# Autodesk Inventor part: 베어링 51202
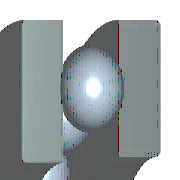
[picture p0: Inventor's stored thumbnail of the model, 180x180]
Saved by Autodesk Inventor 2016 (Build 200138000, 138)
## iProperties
Created: 2012-02
Part Number: 베어링 51202
Material: 강철, 연강
Description: 롤링 베어링 - 플랫 뒷면이 있는 스러스트 볼 베어링
Document SubType Name: Modeling
Standard: KS B 2022
Designer: mduedu
Standards Organization: KS
Language: ko-KR
Size Designation: 51202 - 15 x 32 x 12
Categories: <MemberInstance><Categories><Category DisplayName="샤프트 부품" InternalName="7f7aeb1f-a693-4053-b835-cee3144e0d98" Mnemonic="SHFT"><Category DisplayName="베어링" Inter
Density: 1 g/cm^3
Appearance: 진녹색
IsCustomPart: 1
Author: mduedu
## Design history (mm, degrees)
sketch "스케치1" dims "d3" = 5.28 (= 0.44 x KB)
  geometry: L1 (6, 9.61)-(6, 14.89); L2 (8.64, 12.25)-(3.36, 12.25); L3 (3.6, 16)-(0, 16); L4 (3.6, 7.5)-(0, 7.5); L5 (8.4, 13.35)-(8.4, 16); L6 (8.4, 16)-(12, 16); L7 (12, 16)-(12, 8.5); L8 (12, 8.5)-(8.4, 8.5); L9 (8.4, 8.5)-(8.4, 11.15); L10 (3.6, 16)-(3.6, 13.35); L11 (3.6, 11.15)-(3.6, 7.5); L12 (-1.8, 0)-(10.8, 0) reference; L13 (0, -0.022)-(0, 5.522) reference; 1 further point
  constraints: 22 end point, 5 perpendicular, 2 equal length, 2 midpoint, 2 parallel, 2 point on line, 1 collinear, 10 other
  dimensions: "d8" = 4.8 diameter of L11 L1 (= 0.4 x KB); "d11" = 15 diameter of L4 L12 (= WD); "d12" = 17 diameter of L8 L12 (= KAD1); "d13" = 32 diameter of L3 L12 (= KID1); "d14" = 32 diameter of L6 L12 (= BD); "d15" = 24.5 diameter of point (6, 12.25) L12 (= 0.5 x KID1 + 0.5 x KAD1); "d16" = 6 distance from line of point (6, 12.25) L13 (= 0.5 x KB); "d18" = 12 distance between parallel lines of L7 L13 (= KB)
revolve "본체" stored, may be unused: angle "d9" = 90 deg
revolve "볼" stored, may be unused: angle "d10" = 90 deg
pattern_circular "IDS_ARRAYBALL[SIMPL:T]" dims angle "d2" = 360 deg
body "Solid1"
fillet "모깎기1" dims "d4" = 0.6 (= KRS)
fillet "모깎기2" dims "d5" = 0.6 (= KRS)
other parameters: "WD" = 15 [user parameter; used in 2 equation terms], "KAD1" = 17 [user parameter; used in 3 equation terms], "KID1" = 32 [user parameter; used in 3 equation terms], "BD" = 32 [user parameter; used in 2 equation terms], "KB" = 12 [user parameter; used in 6 equation terms], "KRS" = 0.6 [user parameter; used in 2 equation terms], "d0" = 2.4 (= 0.2 x KB), "d6" = 0, "d7" = 0, "d19" = 0, "d41" = 0, "d42" = 0, "WR" = 7.5 (= 0.5 x WD) [user parameter], "BC" = 1.65e+07 [user parameter], "BBA" = 90 deg [user parameter], "BC0" = 2.7e+07 [user parameter], "BR" = 16 (= 0.5 x BD) [user parameter]
